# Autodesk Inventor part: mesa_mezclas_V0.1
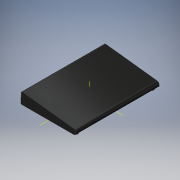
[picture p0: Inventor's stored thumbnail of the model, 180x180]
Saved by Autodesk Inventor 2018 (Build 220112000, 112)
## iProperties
Created: 2018-07
Part Number: mesa_mezclas_V0.1
Material: Generic
Document SubType Name: Modeling
Designer: Gordillo
Density: 1 g/cm^3
Appearance: Default
Author: Gordillo
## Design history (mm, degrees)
sketch "Sketch1"
  geometry: L1 (0, -20.4)-(0, 122.4) reference; L2 (-330.057, 0)-(330.691, 0) reference; L3 (-235, 102)-(235, 102); L4 (235, 102)-(235, 0); L5 (235, 0)-(-235, 0); L6 (-235, 0)-(-235, 102); L7 (-234.751, 7.235)-(-229.81, 91.184); L8 (-220.886, 98.659)-(215.5, 47.117); L9 (215.5, 47.117)-(212.903, 3); L10 (212.903, 3)-(-230.758, 3); A1 r 22.135 centre (212.903, 25.135) between (212.903, 3) and (215.5, 47.117); A2 r 8 centre (-221.824, 90.714) between (-220.886, 98.659) and (-229.81, 91.184); A3 r 4 centre (-230.758, 7) between (-234.751, 7.235) and (-230.758, 3); 3 further points
  constraints: 16 end point, 7 point on circle, 6 tangent, 4 point on line, 3 centre point, 3 parallel, 2 horizontal, 1 collinear, 1 perpendicular, 1 other
  dimensions: "profundo_mesamezcla" = 470 distance of L4.end L5.end; "alto_mesamezclas" = 102 distance of L3.end L4.end; "d2" = 8 radius of A2; "d3" = 4 radius of A3; "d5" = 11.28551 distance from line of L3 A2.centre; "d6" = 25.13497 distance from line of L5 A1.centre; "d7" = 3 distance between parallel lines of L5 L10
extrude "Extrusion1" new body sketch "Sketch1" stored distance "d8" = 704; taper "d9" = 0 deg
sketch "Sketch2"
  geometry: L1 (-3.993, -704)-(-3.993, 0) reference; L2 (443.661, -704)-(0, -704) reference; L3 (230.758, -844.8)-(230.758, 140.8) reference; L4 (-97.959, -352)-(559.755, -352) reference; C1 r 15 at (26.007, -674); C2 r 15 at (26.007, -30); C3 r 15 at (435.508, -674); C4 r 15 at (435.508, -30); 1 further point
  constraints: 4 centre point, 3 symmetric about line, 3 other
  dimensions: "d10" = 30 diameter of C1; "d11" = 30 distance from line of L1 C1.centre; "d12" = 30 distance from line of L2 C1.centre
extrude "Extrusion2" join sketch "Sketch2" distance "d13" = 8; taper "d14" = 0 deg
body "Solid1"
